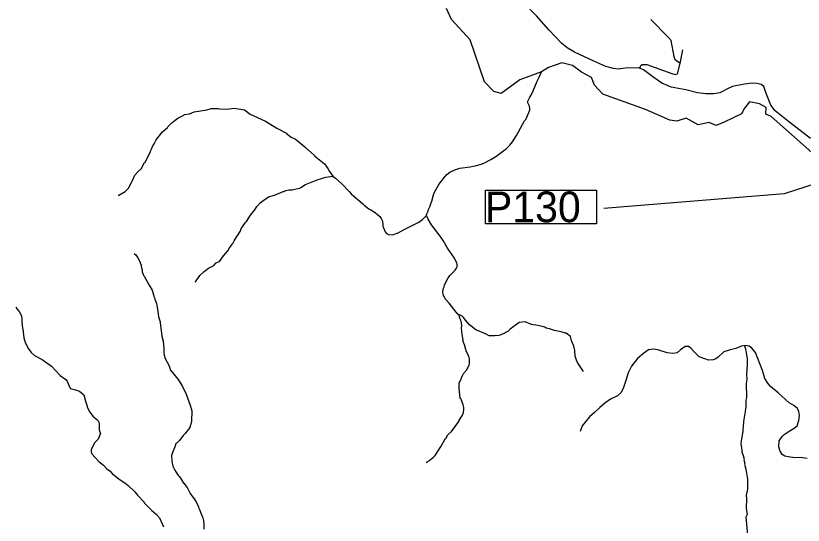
# Model space of a CAD drawing. Extents: x 1248089 to 1457196, y 820910 to 988753.
# Drawn here: x 1341961 to 1350937, y 919465 to 925273 of the extents above; entities that cross this region are included whole.
import ezdxf

# ---------------------------------------------------------------- set-up
doc = ezdxf.new("R2010")
doc.units = 0
for name, color, linetype in [('Exist Hydrographic Creek Single Shore', 7, 'Continuous'), ('Exist Hydrographic Misc Water Feature', 7, 'Continuous'), ('Exist Road Non-System Type 51', 7, 'Continuous'), ('Exist Road Secondary Type 51 Attributed', 7, 'Continuous'), ('Prop Lane Arrow CELL', 7, 'Continuous')]:
    doc.layers.add(name, color=color, linetype=linetype)

msp = doc.modelspace()

# ---------------------------------------------------------------- linework, layer by layer
at = {"layer": 'Exist Hydrographic Creek Single Shore'}
for points in [[(1351168.1, 923594.7), (1350572.5, 924122.6), (1350510.4, 924152.5), (1350512.9, 924228.6), (1350439.3, 924267.9), (1350324, 924290), (1350267.6, 924218.8), (1350233.2, 924154.9), (1350037.5, 924061.1), (1349944.7, 924020.3), (1349863.7, 924057.1), (1349741.1, 924027.6), (1349601.2, 924103.7), (1349495.8, 924071.8), (1349414.8, 924081.6), (1349140.5, 924203.9), (1348653, 924380.7), (1348557.4, 924481.3), (1348523, 924567.2), (1348410.2, 924628.6), (1348307.2, 924704.7), (1348186.9, 924736.6), (1348034.9, 924682.6), (1347953.4, 924633.7), (1347708.6, 924542.7), (1347492.7, 924385.6), (1347409.4, 924409.3), (1347304.4, 924519.8), (1347139.4, 924999.1), (1346927.4, 925229.9), (1346872.4, 925355.8)], [(1350736.5, 917169.3), (1350761.5, 917182), (1350764.6, 917339.5), (1350693.6, 917518.2), (1350504.5, 918756.4), (1350442.6, 918974.2), (1350308.6, 919308.6), (1350288.5, 919561.7), (1350297.5, 919584.5)]]:
    msp.add_lwpolyline(points, dxfattribs=at)
at = {"layer": 'Exist Hydrographic Misc Water Feature'}
for points in [[(1346641.4, 922997.3), (1346646.2, 923015.6), (1346662.9, 923047.2), (1346663, 923055.2), (1346684, 923102.8), (1346684.2, 923110.8), (1346705.3, 923158.3), (1346722.9, 923229.8), (1346735.5, 923261.6), (1346785.4, 923348.4), (1346847.3, 923433), (1346876, 923464.4), (1346908.5, 923489.6), (1346965.1, 923516.4), (1347021.5, 923535.1), (1347141.8, 923552.4), (1347174, 923559.6), (1347198, 923561.1), (1347270.5, 923581.5), (1347310.9, 923598.6), (1347375.6, 923633.2), (1347432.4, 923667.8), (1347554.4, 923761.1), (1347593.2, 923798.2), (1347624.1, 923837.5), (1347669.6, 923908.4), (1347761.2, 924074.4), (1347773.6, 924090.1), (1347811.3, 924169.3), (1347819.9, 924201), (1347820.3, 924217), (1347816.8, 924241.1), (1347797.7, 924281.5), (1347798.1, 924297.5), (1347819.1, 924345.1), (1347835.6, 924368.7), (1347860.6, 924416.1), (1347903.1, 924527.1), (1347928.1, 924574.5), (1347953.4, 924633.7)], [(1343126.8, 923226.5), (1343134.9, 923228.4), (1343207.8, 923270.7), (1343244.6, 923307.9), (1343281.9, 923371.1), (1343290.4, 923394.9), (1343319.8, 923454.1), (1343356.7, 923497.3), (1343393.5, 923532.5), (1343426.8, 923595.7), (1343435, 923603.5), (1343497.5, 923722.1), (1343497.7, 923730.1), (1343510.2, 923753.8), (1343520.9, 923783.7), (1343539.6, 923813.2), (1343560.5, 923856.8), (1343635.1, 923948.3), (1343689.6, 923997.8), (1343695.8, 924007.7), (1343744.8, 924054.5), (1343809.9, 924107), (1343878.6, 924139.5), (1343882.8, 924145.5), (1343943, 924156), (1343995.5, 924178.9), (1344140, 924199.6), (1344188.2, 924214.6), (1344268.3, 924216.7), (1344284.2, 924212.4), (1344368.1, 924206.5), (1344452, 924220.6), (1344568, 924202.1), (1344634.9, 924150.5), (1344809.1, 924072.7), (1344936.2, 923990.9), (1345046.2, 923935.4), (1345048.4, 923930.3), (1345101.2, 923890.1), (1345148.7, 923865.1), (1345188.1, 923836.2), (1345256.8, 923778.6), (1345286.1, 923748), (1345294, 923743.8), (1345364.6, 923680.2), (1345366.9, 923675.2), (1345478.6, 923585.7), (1345517.5, 923532.9), (1345536.7, 923498.4), (1345575, 923444.2)], [(1344005.2, 922237.1), (1344011.4, 922240.8), (1344059, 922311.8), (1344108, 922358.7), (1344156.8, 922395.6), (1344217.4, 922426.2), (1344246.1, 922457.6), (1344282.4, 922472.8), (1344327.8, 922535.7), (1344381.1, 922598.6), (1344389.5, 922614.4), (1344414.2, 922645.7), (1344426.7, 922669.5), (1344434.8, 922677.3), (1344449.6, 922709), (1344463.9, 922726.6), (1344488.9, 922768), (1344493.7, 922771.2), (1344517.8, 922811.8), (1344538.9, 922863), (1344544, 922866.1), (1344576, 922912.1), (1344590.3, 922925.7), (1344637.8, 922998.7), (1344685.2, 923059.6), (1344710, 923097), (1344751.3, 923145.1), (1344842.4, 923208.1), (1344910.7, 923226.5), (1345007.7, 923268.4), (1345015.7, 923268.2), (1345039.9, 923279.6), (1345072.1, 923286.9), (1345112.2, 923290), (1345208.7, 923311.8), (1345211.3, 923316.9), (1345263.7, 923347.6), (1345398.7, 923403.5), (1345495.3, 923433.3), (1345575, 923444.2)], [(1345575, 923444.2), (1345605.1, 923422.9), (1345679.6, 923357.3), (1345761.7, 923271.4), (1345787.1, 923240.9), (1345914.7, 923132), (1345932.3, 923113.7), (1345987.5, 923072.3), (1346009.2, 923061.9), (1346056.5, 923028.9), (1346111.5, 922983.6), (1346125.1, 922963.3), (1346140.3, 922931), (1346140, 922915), (1346143.8, 922906.9), (1346147.1, 922874.9), (1346171.7, 922808.3), (1346185.4, 922792), (1346209, 922777.5), (1346257, 922776.3), (1346321.5, 922798.9), (1346394.4, 922841.2), (1346556.2, 922921.6), (1346596.8, 922950.7), (1346641.4, 922997.3)], [(1347011.7, 921865.9), (1347003.2, 921867.8), (1346981.8, 921892.3), (1346902.1, 921998.1), (1346857.1, 922047.1), (1346834.1, 922095.6), (1346830.9, 922127.7), (1346835.8, 922167.5), (1346844.1, 922183.3), (1346848.6, 922207.2), (1346886.1, 922278.4), (1346910.9, 922311.8), (1346970.2, 922372.5), (1346986.7, 922396.1), (1346993.1, 922412), (1346993.6, 922436), (1346990, 922451.9), (1346963.2, 922508.5), (1346881.6, 922622.3), (1346831.6, 922711.5), (1346800.6, 922760.1), (1346699.5, 922890.5), (1346660.9, 922955.2), (1346641.4, 922997.3)], [(1343312.4, 922564.5), (1343330, 922546.2), (1343353.3, 922513.6), (1343378.3, 922465.1), (1343378.1, 922457.1), (1343389.5, 922428.8), (1343389.2, 922412.8), (1343400.3, 922376.6), (1343403.8, 922352.5), (1343417, 922316.2), (1343420.8, 922308.1), (1343426.2, 922306.2), (1343480.5, 922202.8), (1343515.3, 922146), (1343537.5, 922065.5), (1343545.2, 922049.4), (1343545, 922041.4), (1343564, 921992.9), (1343582.1, 921904.6), (1343588.7, 921842.4), (1343607.4, 921784), (1343605.8, 921777.1), (1343627.9, 921621.6), (1343642.6, 921563.3), (1343648.9, 921479.2), (1343647.8, 921433.1), (1343651.2, 921405.2), (1343658.6, 921378.9), (1343677.7, 921334.5), (1343683.2, 921331.6), (1343708.5, 921281.8), (1343723.4, 921229.5), (1343728.1, 921227.4), (1343811.2, 921127.6), (1343863.4, 921046.4), (1343905.5, 920959.5), (1343950.8, 920832.6), (1343969.4, 920768.1), (1343964.8, 920652.2), (1343958, 920612.4), (1343949.7, 920596.5), (1343949.5, 920588.5), (1343934.9, 920565), (1343891.7, 920509.9), (1343869.2, 920486.4), (1343826, 920431.4), (1343781.1, 920388.4), (1343782.2, 920381), (1343768, 920336.7), (1343762.5, 920333.9), (1343736.3, 920261.4), (1343738.9, 920193.4), (1343751.6, 920137.1), (1343774.7, 920092.6), (1343805.6, 920043.9), (1343840.7, 920003.1), (1343871.4, 919946.4), (1343877.3, 919943), (1343915, 919895.2), (1343948.8, 919826.8), (1344003.3, 919755.5), (1344022.7, 919723.1), (1344045.5, 919674.6), (1344045.4, 919666.6), (1344056.9, 919644.4), (1344074.3, 919595.6), (1344092.6, 919549.4), (1344101, 919518.8), (1344105.6, 919472.4), (1344104.5, 919420.7)], [(1341961.2, 921954.9), (1341978.6, 921926.6), (1341999.9, 921900.1), (1342024.9, 921851.6), (1342032.2, 921819.4), (1342031.2, 921773.4), (1342034.9, 921759.3), (1342034.4, 921735.4), (1342038.2, 921727.3), (1342037.9, 921711.3), (1342041.7, 921703.2), (1342055.2, 921600.9), (1342068.6, 921547.6), (1342104.7, 921475.8), (1342137.8, 921433), (1342175.1, 921400.2), (1342262.1, 921354.3), (1342368.5, 921280), (1342466.2, 921173.8), (1342531.2, 921128.3), (1342546.8, 921107.9), (1342569.5, 921049.5), (1342587, 921025.1), (1342594.8, 921018.9), (1342642.6, 921007.9), (1342686.2, 920992.9), (1342737.4, 920951.7), (1342752.2, 920895.4), (1342750.6, 920890.7), (1342774.5, 920822.9), (1342774.4, 920814.9), (1342797.4, 920766.4), (1342840, 920707.5), (1342885.2, 920672.4), (1342902.9, 920652.1), (1342910.2, 920619.9), (1342912.6, 920551.8), (1342927.7, 920507.5), (1342922.6, 920504.4), (1342902.4, 920448.1), (1342861.6, 920409), (1342819.8, 920330), (1342819.2, 920302), (1342828.8, 920277.8), (1342908.8, 920192), (1342960, 920150.9), (1342997.5, 920107.1), (1343036.1, 920080.8), (1343069.6, 920042.4), (1343077.6, 920040.2), (1343140.4, 919990.8), (1343203.6, 919949.4), (1343242.9, 919918.5), (1343318.4, 919846.1), (1343350.8, 919807.2), (1343424.7, 919728.6), (1343428.5, 919718.4), (1343454, 919691.8), (1343512.7, 919632.6), (1343563.8, 919589.4), (1343598.8, 919548.6), (1343644.7, 919447.6)], [(1346640.6, 920180.3), (1346673, 920201.5), (1346721.9, 920240.5), (1346740.3, 920262), (1346769.1, 920301.4), (1346808.6, 920368.4), (1346814.8, 920374.3), (1346856.5, 920451.4), (1346862.5, 920455.3), (1346887.3, 920494.6), (1346928.3, 920533.7), (1347010.7, 920647.9), (1347012.8, 920655.8), (1347052.2, 920719), (1347064.9, 920750.6), (1347065.3, 920766.6), (1347069.4, 920774.5), (1347070.2, 920806.5), (1347062.9, 920838.7), (1347047.7, 920879), (1347034.4, 920909.2), (1347028.4, 920911.4), (1347015, 921027.7), (1347016.2, 921087.6), (1347039.2, 921131.1), (1347041.5, 921147.1), (1347056.2, 921178.8), (1347066.7, 921196.5), (1347097.4, 921233.8), (1347128.7, 921289.1), (1347133, 921305), (1347134.2, 921361), (1347127, 921393.2), (1347100, 921441.8), (1347077.6, 921520.2), (1347058.8, 921570.6), (1347060.3, 921578.5), (1347048.2, 921638.8), (1347043.9, 921714.9), (1347046.5, 921738.9), (1347043.1, 921771), (1347035.8, 921803.1), (1347024.3, 921827.4), (1347011.7, 921865.9)], [(1348431.1, 921215.9), (1348365.4, 921321.3), (1348353.9, 921345.6), (1348338.9, 921393.9), (1348332.4, 921458.1), (1348321.4, 921506.2), (1348304.4, 921552.7), (1348298.4, 921554.7), (1348283.8, 921615.1), (1348236.6, 921656.1), (1348229.3, 921655), (1348176.9, 921669.5), (1348101.3, 921683.2), (1348045.7, 921704.4), (1348005.9, 921713.4), (1347990, 921721.7), (1347910.6, 921743.5), (1347838.8, 921755.1), (1347767.3, 921782.7), (1347699.3, 921776.2), (1347595.6, 921698.6), (1347569, 921673.2), (1347552.8, 921665.5), (1347532.4, 921650), (1347524.5, 921650.1), (1347484.2, 921633.1), (1347452, 921625.8), (1347428, 921626.3), (1347419.9, 921622.5), (1347355.9, 921623.9), (1347316.4, 921648.8), (1347205.4, 921691.3), (1347134.6, 921748.8), (1347091.7, 921797.8), (1347064.5, 921834.4), (1347048.8, 921846.7), (1347011.7, 921865.9)], [(1350267.9, 921517.2), (1350267.4, 921508.6), (1350280.7, 921474.3), (1350298.2, 921361.9), (1350298.8, 921297.9), (1350290.4, 921186.2), (1350293.1, 921126.1), (1350288.1, 921081.4), (1350288.7, 920922.3), (1350284, 920892.3), (1350284.3, 920818.3), (1350277.2, 920762.5), (1350254.6, 920647.1), (1350253.3, 920583.1), (1350249, 920569.2), (1350248.3, 920535.2), (1350238.8, 920471.5), (1350227.9, 920423.7), (1350227.1, 920391.7), (1350237.5, 920319.5), (1350237.2, 920303.5), (1350254.2, 920259.1), (1350262.9, 920217.3), (1350261.2, 920210.9), (1350269.9, 920169.2), (1350268.1, 920162.9), (1350282.8, 920102.5), (1350300.3, 919990.1), (1350303.3, 919942.1), (1350302, 919878.1), (1350288.3, 919806.5), (1350291.5, 919766.4), (1350285.2, 919658.5), (1350297.5, 919584.5)]]:
    msp.add_lwpolyline(points, dxfattribs=at)
at = {"layer": 'Exist Road Non-System Type 51'}
msp.add_line((1349535.8, 924727), (1349565.9, 924884.5), dxfattribs=at)
for points in [[(1349535.8, 924727), (1349475.6, 924770.6), (1349465.5, 924807.4), (1349432, 924991.7), (1349398.6, 925028.5), (1349201.1, 925229.5)], [(1349073.9, 924670.1), (1349087.3, 924706.9), (1349100.6, 924717), (1349154.2, 924717), (1349438.7, 924616.5), (1349475.6, 924603.1), (1349502.3, 924609.8), (1349535.8, 924727)], [(1350980.7, 920224.3), (1350930.4, 920234.8), (1350819.4, 920239), (1350767, 920243.2), (1350729.3, 920251.6), (1350697.9, 920272.5), (1350670.7, 920316.5), (1350658.1, 920360.6), (1350664.4, 920425.6), (1350697.9, 920475.9), (1350721, 920498.9), (1350777.5, 920536.7), (1350832, 920572.3), (1350869.7, 920599.6), (1350886.4, 920658.3), (1350894.8, 920717), (1350886.4, 920763.1), (1350871.8, 920794.5), (1350829.9, 920830.2), (1350775.4, 920861.6), (1350733.5, 920897.3), (1350651.8, 920972.7), (1350563.9, 921046.1), (1350532.5, 921083.8), (1350498.9, 921136.3), (1350473.8, 921228.5), (1350392.1, 921436.1), (1350352.3, 921484.3), (1350320.9, 921505.2), (1350274.8, 921513.6), (1350232.9, 921505.2), (1350168, 921478), (1350092.6, 921459.1), (1350034, 921440.2), (1349966.9, 921381.5), (1349941.8, 921362.7), (1349910.4, 921350.1), (1349855.9, 921345.9), (1349814, 921360.6), (1349751.2, 921383.6), (1349692.5, 921440.2), (1349654.8, 921484.3), (1349627.6, 921501), (1349592, 921501), (1349539.6, 921465.4), (1349499.8, 921431.9), (1349451.7, 921423.5), (1349384.6, 921431.9), (1349279.9, 921463.3), (1349225.4, 921471.7), (1349175.2, 921463.3), (1349118.6, 921427.7), (1349047.4, 921364.8), (1348980.4, 921278.8), (1348942.7, 921203.3), (1348915.5, 921113.2), (1348890.3, 921035.6), (1348863.1, 920976.9), (1348821.2, 920939.2), (1348741.6, 920901.5), (1348674.6, 920855.3), (1348618, 920809.2), (1348559.4, 920750.5), (1348502.8, 920700.2)], [(1348502.8, 920700.2), (1348452.6, 920639.4), (1348416.9, 920597.5), (1348396, 920534.6)]]:
    msp.add_lwpolyline(points, dxfattribs=at)
at = {"layer": 'Exist Road Secondary Type 51 Attributed'}
for points in [[(1349397.5, 924472.7), (1349324.4, 924505.1), (1349223.7, 924577.5), (1349116, 924657), (1349061.3, 924680), (1348905.9, 924674.7), (1348826.5, 924664.1), (1348775.3, 924671.2), (1348687, 924695.9), (1348549.3, 924754.2), (1348330.4, 924858.4), (1348247.8, 924905.7), (1348180.7, 924960.5), (1348037.7, 925112.4), (1347897.1, 925270.9), (1347819.4, 925348.7)], [(1351019.1, 923873), (1350768.4, 924069.2), (1350616.6, 924189.3), (1350567.2, 924252.9), (1350512.4, 924397.8), (1350486.5, 924467.9), (1350456.5, 924489.1), (1350408.8, 924501.5), (1350354.1, 924503.2), (1350267.6, 924492.6), (1350129.8, 924466.1), (1350089.7, 924446.8), (1349987.3, 924393.8), (1349916.7, 924381.4), (1349826.7, 924381.4), (1349731.3, 924393.8), (1349599.6, 924426.8), (1349431.9, 924460.4), (1349397.5, 924472.7)]]:
    msp.add_lwpolyline(points, dxfattribs=at)
at = {"layer": 'Prop Lane Arrow CELL'}
msp.add_lwpolyline([(1351826.3, 923601.9), (1350720.9, 923244.7), (1348663, 923074.7)], dxfattribs=at)
msp.add_lwpolyline([(1347315.6, 923283.6), (1348581.7, 923283.6), (1348581.7, 922899.7), (1347315.6, 922899.7)], close=True, dxfattribs=at)

# ---------------------------------------------------------------- texts
msp.add_text('P130', height=350, dxfattribs=at).set_placement((1347308.5, 922919.5))

doc.saveas('drawing.dxf')
